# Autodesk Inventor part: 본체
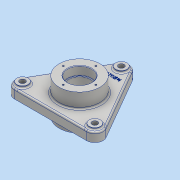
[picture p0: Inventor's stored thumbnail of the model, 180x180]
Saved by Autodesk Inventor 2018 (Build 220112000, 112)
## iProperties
Created: 2023-04
Part Number: 본체
Material: 알루미늄 6061
Document SubType Name: Modeling
Designer: home
Density: 2.7 g/cm^3
Appearance: 알루미늄 - 평지
Mass: 1221.77 g
Surface Area: 648.013 cm^2
Volume: 452.506 cm^3
Author: home
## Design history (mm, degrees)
sketch "스케치7"
  geometry: L1 (0, 0)-(-71.014, -41); L2 (0, 0)-(0, 57.274); L3 (0, 0)-(71.014, -41); L4 (-84.87, -33)-(-13.856, 90); L5 (-71.014, -57)-(71.014, -57); L6 (84.87, -33)-(13.856, 90); A1 r 82 centre (0, 0) between (0, 82) and (-71.014, -41); A2 r 16 centre (0, 82) between (13.856, 90) and (-13.856, 90); A3 r 16 centre (-71.014, -41) between (-84.87, -33) and (-71.014, -57); A4 r 16 centre (71.014, -41) between (71.014, -57) and (84.87, -33); 1 further point
  constraints: 12 end point, 9 point on circle, 4 centre point, 3 coincident, 3 tangent, 2 symmetric about line, 1 horizontal, 1 vertical
  dimensions: "d74" = 82 radius of A1; "d76" = 120 deg angle of L1 L2; "d77" = 120 deg angle of L2 L3
extrude "돌출5" new body sketch "스케치7" distance "d79" = 18; taper "d80" = 0 deg
sketch "스케치8"
  geometry: L1 (-71.014, -57)-(71.014, -57) reference; L2 (84.87, -33)-(13.856, 90) reference; L3 (-13.856, 90)-(-84.87, -33) reference; C1 r 11 at (0, 82); C2 r 11 at (-71.014, -41); C3 r 11 at (71.014, -41); A1 r 16 centre (71.014, -41) between (71.014, -57) and (84.87, -33) reference; A2 r 16 centre (0, 82) between (13.856, 90) and (-13.856, 90) reference; A3 r 16 centre (-71.014, -41) between (-84.87, -33) and (-71.014, -57) reference; 1 further point
  constraints: 3 centre point, 3 coincident
  dimensions: "d81" = 11 radius of C1; "d82" = 11 radius of C2; "d83" = 11 radius of C3
extrude "돌출6" join sketch "스케치8" distance "d84" = 4; taper "d85" = 0 deg
sketch "스케치9"
  geometry: L1 (71.014, -57)-(-71.014, -57) reference; L2 (13.856, 90)-(84.87, -33) reference; L3 (-84.87, -33)-(-13.856, 90) reference; C1 r 11 at (-71.014, -41) reference; A1 r 16 centre (71.014, -41) between (71.014, -57) and (84.87, -33) reference; A2 r 16 centre (0, 82) between (13.856, 90) and (-13.856, 90) reference; A3 r 16 centre (-71.014, -41) between (-84.87, -33) and (-71.014, -57) reference; 4 further points
  constraints: 2 coincident
hole "구멍7" sketch "스케치9" at (0, 82), (71.014, -41), (-71.014, -41) diameter "d86" = 11; stored, may be unused: countersink angle "d90" = 90 deg, drill point angle "d92" = 118 deg; dims "d87" = 6, "d88" = 47, "d89" = 17, "d91" = 70
node "작업 평면4"
sketch "스케치10"
  geometry: C1 r 45 at (0, 0); 1 further point
  constraints: 1 centre point, 1 coincident
  dimensions: "d94" = 45 radius of C1
extrude "돌출7" join sketch "스케치10" distance "d95" = 5; taper "d96" = 0 deg
sketch "스케치11"
  geometry: C1 r 45 at (0, 0) reference; C2 r 40 at (0, 0); 1 further point
  constraints: 1 centre point, 1 coincident
  dimensions: "d97" = 40 radius of C2
extrude "돌출8" join sketch "스케치11" distance "d98" = 23; taper "d99" = 0 deg; dims "d100" = 47, "d101" = 0
hole "구멍8" diameter "d104" = 42; stored, may be unused: countersink angle "d108" = 90 deg, drill point angle "d110" = 118 deg; dims "d102" = 10, "d103" = 10, "d105" = 6, "d106" = 47, "d107" = 17, "d109" = 70
hole "구멍9" diameter "d113" = 42; stored, may be unused: countersink angle "d117" = 90 deg, drill point angle "d119" = 118 deg; dims "d111" = 10, "d112" = 10, "d114" = 6, "d115" = 47, "d116" = 17, "d118" = 70
chamfer "모따기1" distance "d120" = 1; stored, may be unused: second distance "d121" = 2, angle "d122" = 45 deg
fillet "모깎기2" dims "d124" = 3
fillet "모깎기3" dims "d125" = 3
sketch "스케치12"
  geometry: L1 (0, 0)-(0, 32); 1 further point
  constraints: 2 end point, 1 coincident, 1 vertical
  dimensions: "d126" = 32 distance of L1.start L1.end
hole "구멍10" sketch "스케치12" at (0, 32) diameter "d127" = 3.242; stored, may be unused: countersink angle "d131" = 90 deg, drill point angle "d133" = 118 deg; dims "d128" = 8, "d129" = 47, "d130" = 17, "d132" = 10
node "작업 평면5"
sketch "스케치13"
  geometry: 2 further points
  constraints: 1 vertical alignment, 1 other
  dimensions: "d137" = 60 distance of point (0, 60) point (0, 0)
feature "엠보싱1" sketch "스케치13" dims "d74" = 82, "d76" = 120 deg, "d77" = 120 deg, "d138" = 0.5, "d139" = 0
fillet "모깎기4" dims "d140" = 0.6
fillet "모깎기5" dims "d141" = 0.6
fillet "모깎기6" dims "d142" = 3
node "솔리드2"
pattern_circular "원형 패턴1" dims angle "d135" = 360 deg
mirror "미러1"
node "투영된 루프5"
node "투영된 루프6"
node "투영된 루프7"
other parameters: "d75" = 16, "d78" = 16, "d93" = 5
